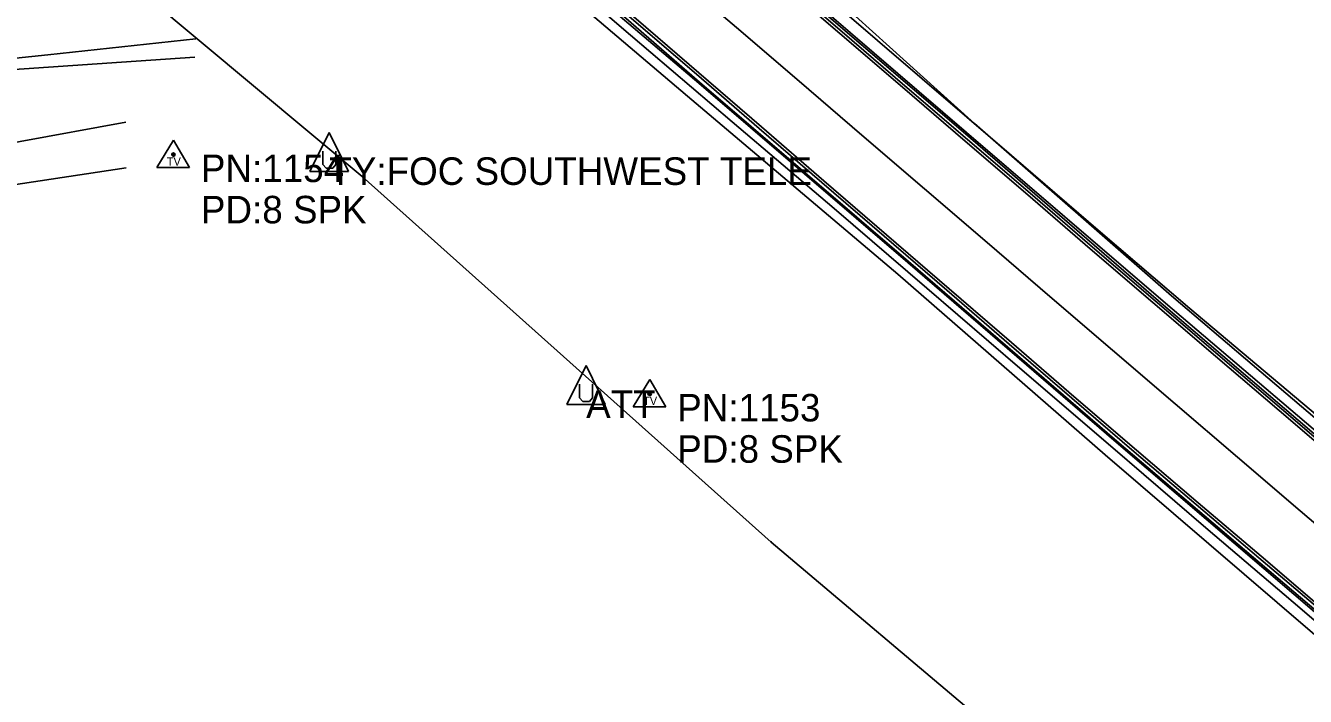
# Model space of a CAD drawing. Extents: x 878399 to 889864, y 1564003 to 1567413.
# Drawn here: x 884685 to 884917.5, y 1565318.8 to 1565440.6 of the extents above; entities that cross this region are included whole.
import ezdxf

# ---------------------------------------------------------------- set-up
doc = ezdxf.new("R2010")
doc.units = 0
for name, color, linetype in [('S_DITCHLINE', 7, 'Continuous'), ('S_EDGE_CONCRETE', 7, 'Continuous'), ('S_EDGE_PAVEMENT', 7, 'Continuous'), ('S_FIBER_OPTIC_CABLE', 7, 'Continuous'), ('S_PAVEMENT_CROWN', 7, 'Continuous'), ('S_SECONDARY_CTL', 7, 'Continuous'), ('S_SECONDARY_CTL_ANNOT', 7, 'Continuous'), ('S_SHOULDER', 7, 'Continuous'), ('S_TRAILS', 7, 'Continuous'), ('S_UTILITY_POLE', 7, 'Continuous'), ('S_UTILITY_POLE_ANNOT', 7, 'Continuous'), ('S_UTL_PT_SYM', 7, 'Continuous')]:
    doc.layers.add(name, color=color, linetype=linetype)

msp = doc.modelspace()

# ---------------------------------------------------------------- linework, layer by layer
at = {"layer": 'S_DITCHLINE'}
for points in [[(884929.2, 1565361.71), (884912.86, 1565375.45), (884896.52, 1565389.2), (884880.31, 1565403.1), (884864.11, 1565417.01), (884847.9, 1565430.92), (884831.69, 1565444.83), (884818.34, 1565456.6), (884804.99, 1565468.36), (884791.26, 1565479.72), (884777.52, 1565491.09), (884767.03, 1565500.26), (884756.54, 1565509.43), (884746.04, 1565518.6), (884735.55, 1565527.77), (884723.63, 1565537.52), (884711.72, 1565547.27), (884706.92, 1565551.05)], [(884931.14, 1565322.32), (884915.28, 1565335.85), (884899.42, 1565349.39), (884882.54, 1565363.89), (884865.66, 1565378.39), (884848.78, 1565392.9), (884831.9, 1565407.4), (884813.4, 1565423.14), (884794.91, 1565438.87), (884783.2, 1565448.95), (884771.49, 1565459.02), (884759.78, 1565469.09), (884748.07, 1565479.17), (884729.25, 1565494.97), (884710.42, 1565510.77), (884693.84, 1565525.36), (884689.13, 1565529.56)], [(884715.98, 1565438.16), (884702.53, 1565436.73), (884689.09, 1565435.31), (884675.64, 1565433.89), (884662.2, 1565432.47), (884645.57, 1565431.23), (884628.93, 1565429.99), (884612.3, 1565428.74), (884595.67, 1565427.5)], [(884715.76, 1565434.83), (884702.47, 1565433.93), (884689.18, 1565433.03), (884675.89, 1565432.13), (884662.6, 1565431.23), (884645.79, 1565430.06), (884628.99, 1565428.9), (884612.18, 1565427.73), (884595.37, 1565426.56), (884576.96, 1565425.22), (884558.55, 1565423.88), (884540.14, 1565422.54), (884521.73, 1565421.2), (884504.59, 1565420.79), (884487.45, 1565420.37), (884470.31, 1565419.96), (884453.17, 1565419.55), (884434.83, 1565419.04), (884416.48, 1565418.52), (884398.13, 1565418.01), (884379.78, 1565417.5), (884361.38, 1565410.86), (884342.98, 1565404.22)]]:
    msp.add_lwpolyline(points, dxfattribs=at)
at = {"layer": 'S_EDGE_CONCRETE'}
for points in [[(884706.6, 1565551.45), (884725.44, 1565537.13), (884744.17, 1565521.12), (884782.46, 1565488.91), (884820.33, 1565456.29), (884857.4, 1565422.83), (884893.19, 1565391.5), (884931.44, 1565358.94), (884969.96, 1565327.51), (885007.93, 1565294.95), (885045.65, 1565262.19), (885083.76, 1565229.98), (885121.86, 1565197.67), (885159.74, 1565165.3), (885198.19, 1565133.4), (885236.59, 1565102.25), (885296.12, 1565053.84), (885311.12, 1565043.35)], [(884705.4, 1565550.04), (884723.26, 1565534.58), (884742.1, 1565518.69), (884780.16, 1565486.23), (884818.14, 1565453.73), (884855.98, 1565421.17), (884892.08, 1565390.2), (884930.32, 1565357.68), (884968.08, 1565325.3), (885005.99, 1565292.69), (885044.06, 1565260.33), (885082.07, 1565227.99), (885120, 1565195.47), (885157.99, 1565163.2), (885196.4, 1565131.24), (885234.81, 1565099.94), (885295.36, 1565052.86), (885310.26, 1565042.23)], [(884689.18, 1565530.77), (884695.4, 1565525.38), (884733.42, 1565492.91), (884769.21, 1565462.51), (884807.31, 1565430.15), (884845.29, 1565397.58), (884883.12, 1565364.93), (884920.9, 1565332.67), (884959.15, 1565300.1), (884997.09, 1565267.66), (885035.26, 1565235.41), (885073.28, 1565202.9), (885111.19, 1565170.37), (885149.63, 1565138.23), (885187.82, 1565106.01), (885227.08, 1565074.25), (885266.64, 1565043.69), (885278.89, 1565034.31)], [(884688.03, 1565529.41), (884693.66, 1565523.34), (884731.61, 1565490.8), (884767.2, 1565460.17), (884805.29, 1565427.8), (884843.47, 1565395.44), (884881.16, 1565362.62), (884918.8, 1565330.29), (884957.02, 1565297.6), (884994.98, 1565265.2), (885032.99, 1565232.77), (885071.05, 1565200.29), (885109.01, 1565167.81), (885147.48, 1565135.65), (885185.66, 1565103.41), (885224.98, 1565071.52), (885264.55, 1565040.98), (885276.98, 1565031.83)]]:
    msp.add_lwpolyline(points, dxfattribs=at)
at = {"layer": 'S_EDGE_PAVEMENT'}
for points in [[(884673.76, 1565575.86), (884685.2, 1565566.15), (884696.63, 1565556.44), (884708.06, 1565546.72), (884719.51, 1565537.03), (884730.93, 1565527.29), (884742.33, 1565517.55), (884753.72, 1565507.79), (884765.12, 1565498.04), (884776.53, 1565488.26), (884787.91, 1565478.49), (884799.29, 1565468.72), (884810.66, 1565458.95), (884822.04, 1565449.18), (884833.38, 1565439.44), (884844.76, 1565429.68), (884856.14, 1565419.92), (884867.5, 1565410.14), (884878.86, 1565400.36), (884890.22, 1565390.58), (884901.62, 1565380.84), (884913.16, 1565370.98), (884924.56, 1565361.24)], [(884684.78, 1565565.87), (884696.21, 1565556.16), (884707.64, 1565546.44), (884719.09, 1565536.75), (884730.51, 1565527.01), (884741.91, 1565517.27), (884753.31, 1565507.51), (884764.7, 1565497.76), (884776.12, 1565487.98), (884787.5, 1565478.21), (884798.87, 1565468.44), (884810.25, 1565458.67), (884821.62, 1565448.9), (884832.97, 1565439.16), (884844.35, 1565429.4), (884855.73, 1565419.63), (884867.09, 1565409.85), (884878.45, 1565400.07), (884889.81, 1565390.29), (884901.21, 1565380.55), (884912.75, 1565370.69), (884924.15, 1565360.95)], [(884682.03, 1565539.31), (884693.47, 1565529.6), (884704.87, 1565519.86), (884716.32, 1565510.17), (884727.78, 1565500.49), (884739.19, 1565490.75), (884750.54, 1565480.95), (884761.87, 1565471.16), (884773.23, 1565461.36), (884784.59, 1565451.58), (884795.96, 1565441.8), (884807.33, 1565432.02), (884818.72, 1565422.19), (884830.07, 1565412.4), (884841.43, 1565402.6), (884852.78, 1565392.81), (884864.13, 1565383.02), (884875.48, 1565373.23), (884886.85, 1565363.46), (884898.06, 1565353.93), (884909.48, 1565344.22), (884920.89, 1565334.51)], [(884681.61, 1565539.03), (884693.05, 1565529.33), (884704.45, 1565519.58), (884715.9, 1565509.89), (884727.36, 1565500.21), (884738.77, 1565490.47), (884750.12, 1565480.67), (884761.46, 1565470.88), (884772.81, 1565461.08), (884784.18, 1565451.3), (884795.55, 1565441.52), (884806.91, 1565431.74), (884818.31, 1565421.91), (884829.66, 1565412.11), (884841.01, 1565402.32), (884852.37, 1565392.52), (884863.72, 1565382.73), (884875.07, 1565372.95), (884886.44, 1565363.18), (884897.65, 1565353.64), (884909.07, 1565343.93), (884920.49, 1565334.22)]]:
    msp.add_lwpolyline(points, dxfattribs=at)
at = {"layer": 'S_FIBER_OPTIC_CABLE'}
for p, q in [((884746.2, 1565413.17), (884630.03, 1565510.1)), ((884820.5, 1565346.79), (884746.2, 1565413.17)), ((884909.8, 1565271.35), (884820.5, 1565346.79))]:
    msp.add_line(p, q, dxfattribs=at)
at = {"layer": 'S_PAVEMENT_CROWN'}
msp.add_lwpolyline([(884802.78, 1565449.96), (884814.18, 1565440.22), (884825.58, 1565430.47), (884836.97, 1565420.72), (884848.34, 1565410.95), (884859.72, 1565401.18), (884871.09, 1565391.42), (884882.47, 1565381.66), (884893.86, 1565371.91), (884905.21, 1565362.19), (884916.6, 1565352.44), (884928, 1565342.7)], dxfattribs=at)
at = {"layer": 'S_SECONDARY_CTL'}
for p, q in [((884711.88, 1565419.78), (884708.87, 1565414.83)), ((884711.88, 1565419.78), (884714.83, 1565414.83)), ((884708.87, 1565414.83), (884714.83, 1565414.83)), ((884798.41, 1565376.31), (884795.4, 1565371.36)), ((884798.41, 1565376.31), (884801.35, 1565371.36)), ((884795.4, 1565371.36), (884801.35, 1565371.36))]:
    msp.add_line(p, q, dxfattribs=at)
for centre, radius in [((884711.88, 1565417.17), 0.311), ((884711.88, 1565417.17), 0.183), ((884711.88, 1565417.17), 0.103), ((884798.41, 1565373.7), 0.311), ((884798.41, 1565373.7), 0.183), ((884798.41, 1565373.7), 0.103)]:
    msp.add_circle(centre, radius, dxfattribs=at)
at = {"layer": 'S_SHOULDER'}
for points in [[(884315.55, 1565882.9), (884321.54, 1565877.6), (884359.45, 1565845), (884397.59, 1565812.6), (884435.73, 1565780.26), (884473.65, 1565747.79), (884511.66, 1565715.22), (884549.66, 1565682.72), (884587.52, 1565650.1), (884625.56, 1565617.69), (884664.18, 1565584.36), (884702.58, 1565551.39), (884704.78, 1565549.31), (884722.81, 1565534.04), (884741.48, 1565517.97), (884779.63, 1565485.61), (884817.88, 1565453.42), (884855.77, 1565420.91), (884891.75, 1565389.81), (884929.91, 1565357.22)], [(884655.38, 1565560.72), (884687.38, 1565533.95), (884690.03, 1565531.77), (884696.22, 1565526.35), (884734.31, 1565493.96), (884769.75, 1565463.15), (884807.48, 1565430.34), (884845.42, 1565397.74), (884883.27, 1565365.1), (884921.11, 1565332.91)]]:
    msp.add_lwpolyline(points, dxfattribs=at)
at = {"layer": 'S_TRAILS'}
for points in [[(884703.25, 1565423.08), (884684.03, 1565419.52), (884664.82, 1565415.97), (884648.24, 1565415.94), (884631.66, 1565415.92), (884615.09, 1565415.89), (884598.51, 1565415.87), (884578.88, 1565416.36), (884559.25, 1565416.85), (884539.62, 1565417.34), (884519.99, 1565417.83), (884502.9, 1565416.7), (884485.81, 1565415.57), (884468.72, 1565414.44), (884451.64, 1565413.31), (884430.23, 1565409.24), (884408.83, 1565405.18)], [(884703.28, 1565414.74), (884684.46, 1565411.91), (884665.64, 1565409.08), (884649.06, 1565409.13), (884632.48, 1565409.18), (884615.9, 1565409.23), (884599.32, 1565409.28), (884579.72, 1565409.84), (884560.12, 1565410.39), (884540.53, 1565410.94), (884520.93, 1565411.49), (884503.63, 1565410.76), (884486.32, 1565410.03), (884469.02, 1565409.31), (884451.72, 1565408.58), (884432.46, 1565404.21), (884413.21, 1565399.84)]]:
    msp.add_lwpolyline(points, dxfattribs=at)
at = {"layer": 'S_UTILITY_POLE'}
for p, q in [((884740.21, 1565421.19), (884736.68, 1565414.1)), ((884740.21, 1565421.19), (884743.7, 1565414.1)), ((884739.01, 1565415.34), (884739.01, 1565417.78)), ((884741.37, 1565417.78), (884741.37, 1565415.34)), ((884736.68, 1565414.1), (884743.7, 1565414.1)), ((884739.63, 1565414.68), (884739.01, 1565415.34)), ((884740.83, 1565414.68), (884739.63, 1565414.68)), ((884741.37, 1565415.34), (884740.83, 1565414.68)), ((884786.86, 1565378.86), (884783.33, 1565371.77)), ((884786.86, 1565378.86), (884790.34, 1565371.77)), ((884785.66, 1565373.01), (884785.66, 1565375.45)), ((884788.02, 1565375.45), (884788.02, 1565373.01)), ((884786.28, 1565372.35), (884785.66, 1565373.01)), ((884787.48, 1565372.35), (884786.28, 1565372.35)), ((884788.02, 1565373.01), (884787.48, 1565372.35)), ((884783.33, 1565371.77), (884790.34, 1565371.77))]:
    msp.add_line(p, q, dxfattribs=at)
at = {"layer": 'S_UTL_PT_SYM'}
for points in [[(884746.2, 1565413.17), (884746.2, 1565413.22), (884746.2, 1565413.17), (884746.15, 1565413.17), (884746.2, 1565413.17), (884746.2, 1565413.12), (884746.2, 1565413.17), (884746.25, 1565413.17)], [(884820.5, 1565346.79), (884820.5, 1565346.84), (884820.5, 1565346.79), (884820.45, 1565346.79), (884820.5, 1565346.79), (884820.5, 1565346.74), (884820.5, 1565346.79), (884820.55, 1565346.79)]]:
    msp.add_lwpolyline(points, dxfattribs=at)

# ---------------------------------------------------------------- texts
at = {"layer": 'S_SECONDARY_CTL'}
for p in [(884710.68, 1565415.16), (884797.2, 1565371.69)]:
    msp.add_text('TV', height=1.5, rotation=360, dxfattribs=at).set_placement(p)
at = {"layer": 'S_SECONDARY_CTL_ANNOT'}
for s, p in [('PN:1154', (884716.88, 1565412.17)), ('PD:8 SPK', (884716.88, 1565404.67)), ('PN:1153', (884803.41, 1565368.7)), ('PD:8 SPK', (884803.41, 1565361.2))]:
    msp.add_text(s, height=5, dxfattribs=at).set_placement(p)
at = {"layer": 'S_UTILITY_POLE_ANNOT'}
for s, p in [('TY:FOC SOUTHWEST TELE', (884740.21, 1565411.66)), ('ATT', (884786.86, 1565369.33))]:
    msp.add_text(s, height=5, dxfattribs=at).set_placement(p)

doc.saveas('drawing.dxf')
